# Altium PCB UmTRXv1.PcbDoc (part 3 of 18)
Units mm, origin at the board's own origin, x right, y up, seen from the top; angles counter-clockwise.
Board outline 172 x 113 mm, 6 copper layers (Top Layer, GND, MidLayer1, Mid-Layer 2, InternalPlane2, Bottom Layer); 766 components, 613 nets, 3008 pads, 1360 vias.
Unrouted connection lines stored in the file: 2.
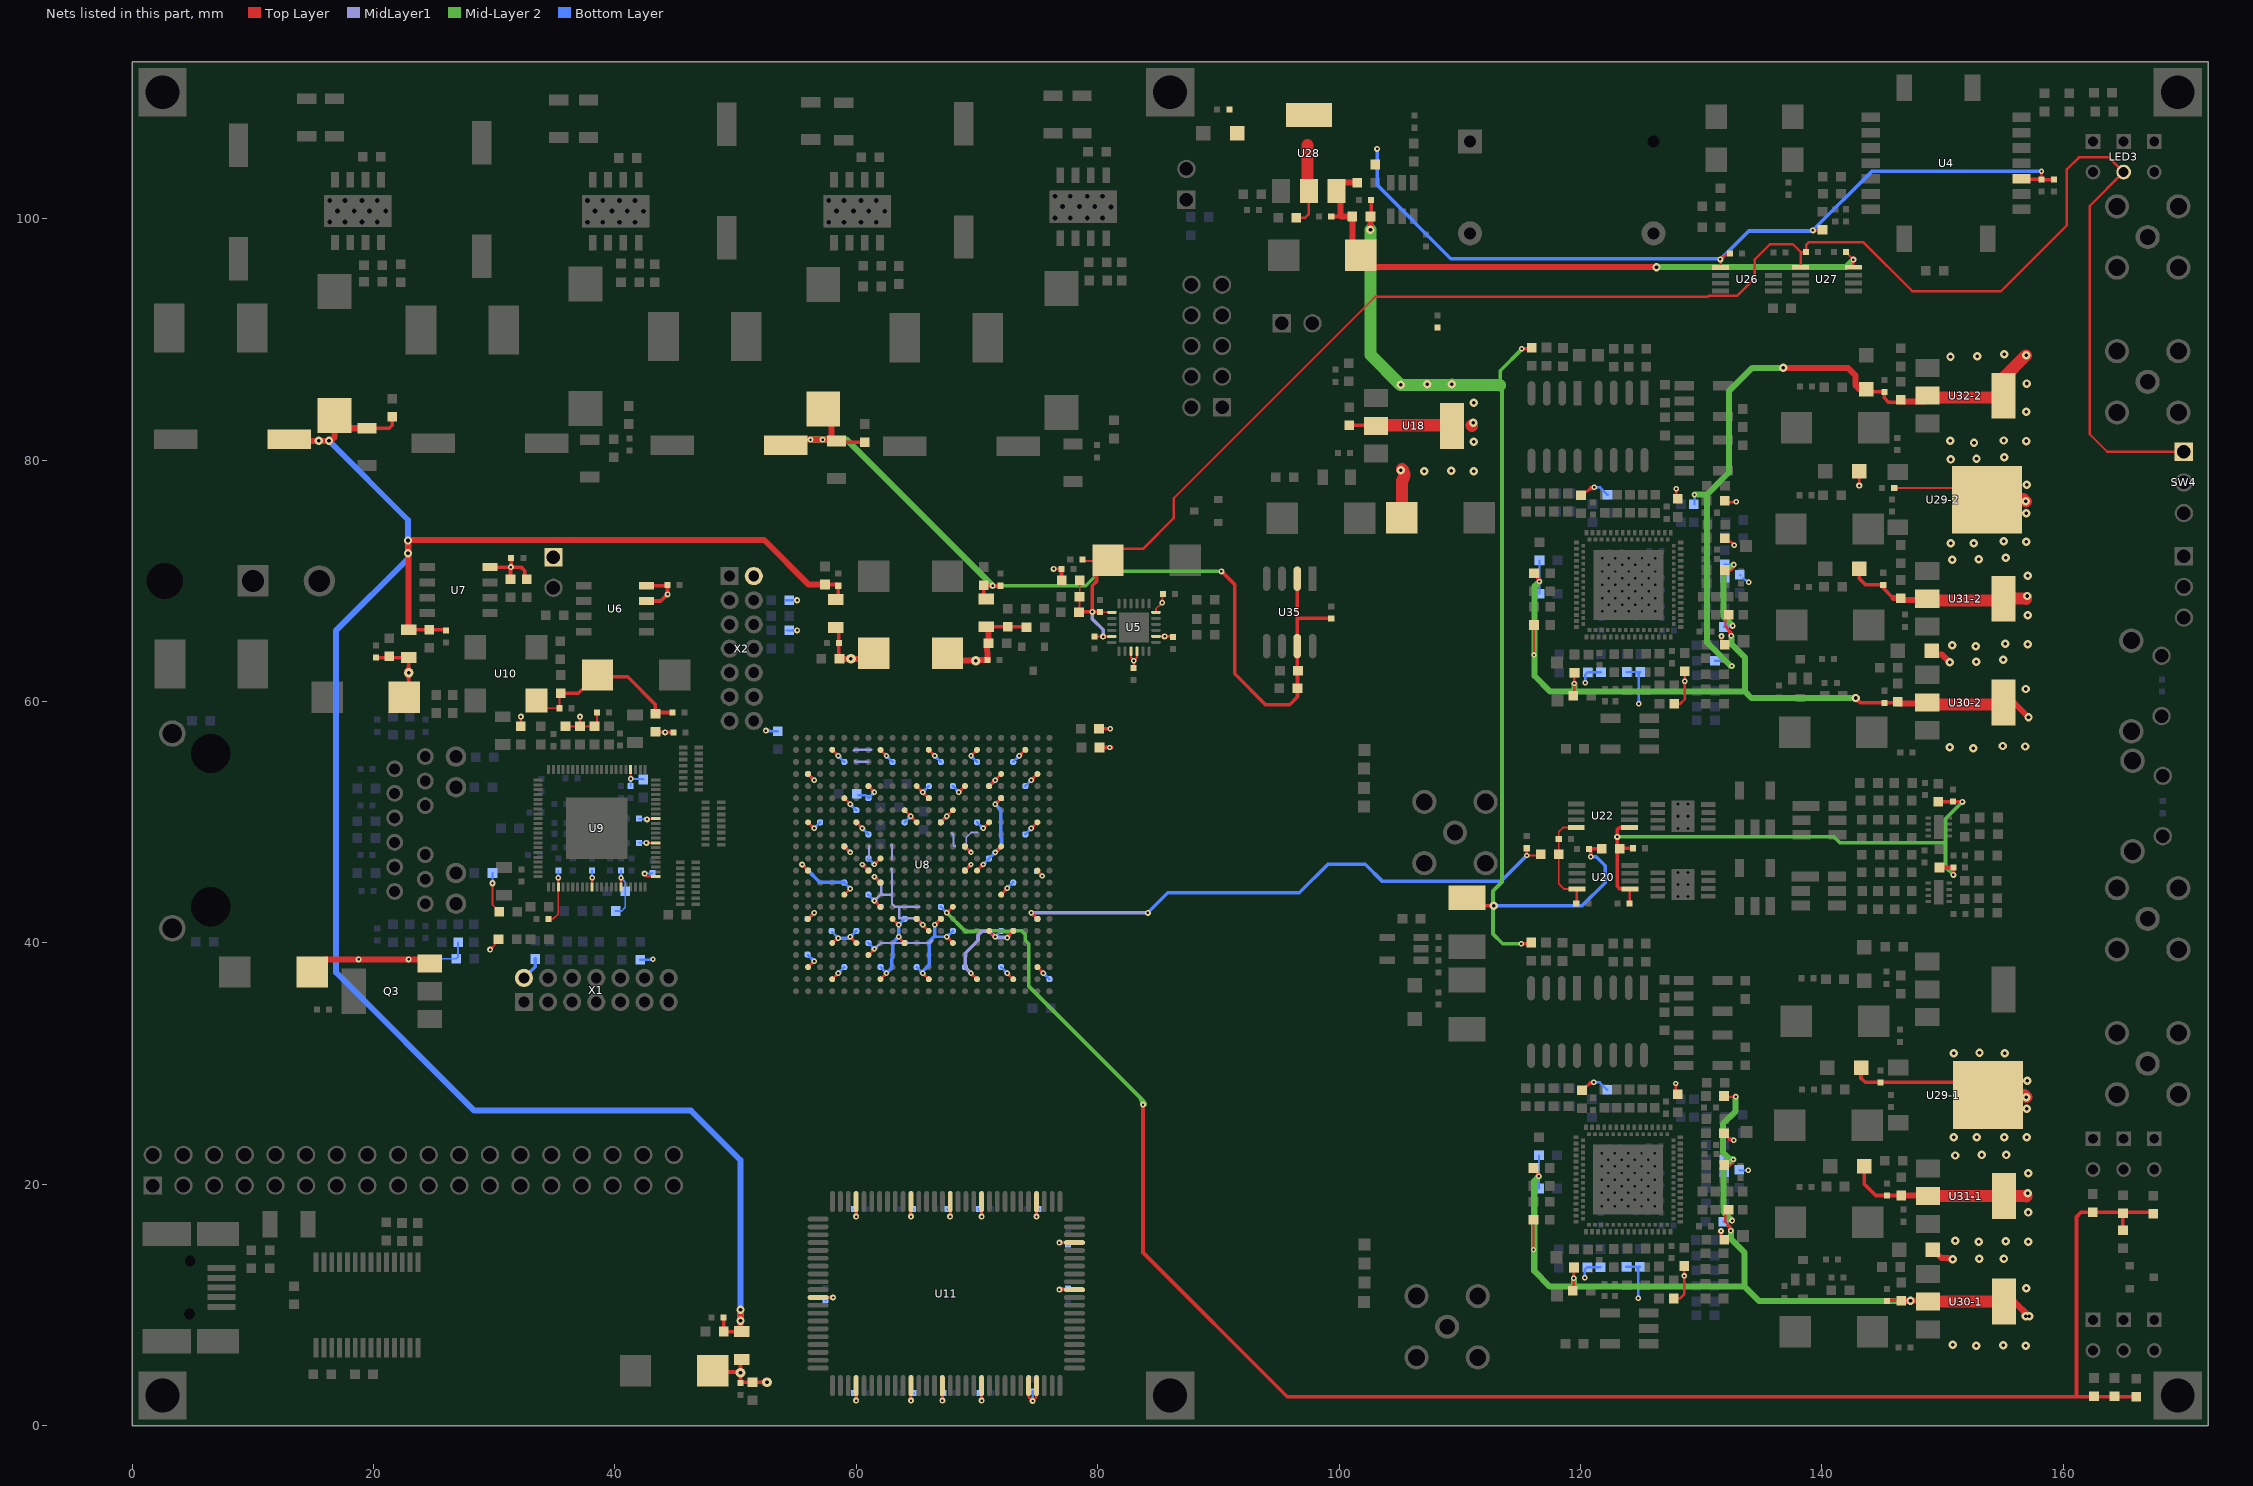
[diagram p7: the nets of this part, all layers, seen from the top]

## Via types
v1: diameter 0.45, hole 0.2, Top Layer to Bottom Layer, tented both sides, 554 vias
v2: diameter 0.5, hole 0.2, Top Layer to Bottom Layer, tented both sides, 468 vias
v3: diameter 0.7, hole 0.3, Top Layer to Bottom Layer, tented both sides, 206 vias
v4: diameter 0.4, hole 0.2, Top Layer to Bottom Layer, tented both sides, 82 vias
v5: diameter 0.8, hole 0.3, Top Layer to Bottom Layer, tented both sides, 16 vias
v6: diameter 0.6, hole 0.25, Top Layer to Bottom Layer, tented both sides, 16 vias
v7: diameter 0.5, hole 0.3, Top Layer to Bottom Layer, tented both sides, 8 vias
v8: diameter 0.7, hole 0.3, Top Layer to Bottom Layer, 4 vias
v9: diameter 0.6, hole 0.3, Top Layer to Bottom Layer, tented both sides, 4 vias
v10: diameter 0.5, hole 0.2, Top Layer to Bottom Layer, 2 vias

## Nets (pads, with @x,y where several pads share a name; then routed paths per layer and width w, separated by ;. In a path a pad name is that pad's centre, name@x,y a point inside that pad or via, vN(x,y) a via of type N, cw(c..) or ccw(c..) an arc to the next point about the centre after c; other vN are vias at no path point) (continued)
+1,8VALMS-2: C67-2.1 C72-2.1 L14-2.1 L15-2.1 R101-2.2 U32-2.2 | length 58.8
  Top Layer w0.3: C67-2.1@143.9,85.8 144.037,85.663 145.161,85.663 145.161,85.167 145.507,84.821 146.322,84.821 R101-2.2@146.352,84.85
  Top Layer w0.5: v3(136.8,87.65) 142.15,87.65 142.8,87 142.8,86.2 143.15,85.85 C67-2.1@144.05,85.85 ; R101-2.2@146.352,84.85 148.55,84.85 U32-2.2@148.55,85.2
  Top Layer w1: U32-2.2@148.55,85.2 U32-2.2@154.85,85.2 ; U32-2.2@155.05,85.35 155.05,86.82 v3(156.925,88.696)
  Mid-Layer 2 w0.5: v1(129.45,77.15) 130.462,77.15 ; v1(132.55,62.95) 132.437,62.95 130.483,64.904 130.483,77.13 130.462,77.15 ; v3(136.8,87.65) 136.8,87.6 136.75,87.65 134.25,87.65 132.3,85.7 132.3,78.988 130.462,77.15
  Bottom Layer w0.2: v1@129.362,77.062 cw(c129.148,76.848) 129.45,76.848 cw(c129.752,76.848) v1@129.538,77.062 ; L15-2.1@129.45,76.35 v1(129.45,77.15) ; L14-2.1@131.146,63.38 132.12,63.38 v1(132.55,62.95) ; v1@132.425,62.95 ccw(c132.123,62.95) 132.337,63.163 ccw(c132.55,63.377) v1@132.55,63.075
  other v3: 152.611,81.442 150.65,81.6 156.925,81.592 155.063,81.636 156.925,84.018 156.969,86.357 150.661,88.589 152.87,88.632 155.106,88.782
+1,8VDLMS-1: C66-1.1 C71-1.1 L11-1.2 L16-1.2 L18-1.2 L19-1.2 L20-1.2 R100-1.2 U31-1.2 | length 23.3
  Top Layer w0.2: v2@131.542,16.03 cw(c131.273,15.761) L19-1.2@131.654,15.761 ; L19-1.2@131.654,15.495 v2@131.654,16.069 ; L19-1.2@131.654,15.787 cw(c131.997,15.787) v2@131.754,16.03 ; L19-1.2@131.907,15.588 L19-1.2@132.037,15.458 ; L16-1.2@131.907,24.188 131.907,24.143 132.4,23.65 ; L16-1.2@131.974,24.076 ccw(c132.7,24.801) v1@132.7,23.775 ; 132.316,23.734 ccw(c132.7,24.118) v1@132.7,23.575 ; v1@132.611,23.562 ccw(c132.4,23.353) 132.4,23.65 ; v1@132.611,23.738 cw(c132.4,23.947) 132.4,23.65 ; v1(132.7,23.65) 132.4,23.65
  Top Layer w0.3: C66-1.1@143.5,21.5 143.5,20.05 144.473,19.077 C71-1.1@145.39,19.077 ; C71-1.1@145.35,19.077 R100-1.2@146.59,19.077
  Top Layer w0.5: R100-1.2@146.59,19.077 148.74,19.077 U31-1.2@148.79,19.027
  Top Layer w1: U31-1.2@148.79,19.027 U31-1.2@155.09,19.027 156.938,19.027 v3@156.972,18.993
  Bottom Layer w0.15: L18-1.2@133.161,21.208 133.211,21.158 v1(133.911,21.158) ; v1@133.805,21.052 ccw(c133.549,20.796) 133.549,21.158 ccw(c133.549,21.52) v1@133.805,21.264
  Bottom Layer w0.2: v1@120.273,12.347 ccw(c120.059,12.56) 120.361,12.56 ccw(c120.663,12.56) v1@120.449,12.347 ; v1(120.361,12.258) 120.361,12.942 L20-1.2@120.557,13.138 L11-1.2@121.657,13.138
  other v2: 131.648,16.136
  other v3: 152.995,15.244 157.109,15.244 155.247,15.287 151.046,15.33 157.109,17.669 157.059,19.253 157.116,20.917 151.046,22.39 153.255,22.434 155.29,22.434
+1,8VDLMS-2: C66-2.1 C71-2.1 L11-2.2 L16-2.2 L18-2.2 L19-2.2 L20-2.2 R100-2.2 U31-2.2 | length 22.6
  Top Layer w0.2: v2@131.581,65.322 cw(c131.312,65.053) L19-2.2@131.693,65.053 ; L19-2.2@131.693,64.787 v2@131.693,65.361 ; L19-2.2@131.693,65.079 cw(c132.036,65.079) v2@131.793,65.322 ; L19-2.2@131.946,64.88 L19-2.2@132.076,64.75 ; L16-2.2@131.946,73.48 131.946,73.354 132.05,73.25 132.45,73.25 132.65,73.05 v1@132.65,72.85 ; v1@132.625,72.95 ccw(c132.323,72.95) 132.537,73.163 ccw(c132.75,73.377) v1@132.75,73.075
  Top Layer w0.3: C66-2.1@143.1,71 143.1,70.2 143.624,69.676 C71-2.1@145.09,69.676 145.09,69.41 145.924,68.576
  Top Layer w0.5: 145.924,68.576 R100-2.2@146.54,68.576 ; R100-2.2@146.34,68.426 148.49,68.426 U31-2.2@148.54,68.376
  Top Layer w1: U31-2.2@148.54,68.376 U31-2.2@154.84,68.376 ; U31-2.2@155.04,68.526 156.888,68.526 v3@156.922,68.492
  Bottom Layer w0.15: L18-2.2@133.2,70.5 L18-2.2@133.25,70.45 ; 133.699,70.001 ccw(c133.943,70.245) v1(133.95,69.9) ; v1@133.947,70.05 cw(c133.933,70.733) 133.45,70.25 133.775,69.925 133.85,70 v1@133.95,70.1
  Bottom Layer w0.2: v1@120.312,61.638 ccw(c120.098,61.852) 120.4,61.852 ccw(c120.702,61.852) v1@120.488,61.638 ; v1(120.4,61.55) 120.4,62.234 L20-2.2@120.596,62.43 L11-2.2@121.696,62.43
  other v1: 132.75,72.95
  other v2: 131.687,65.428
  other v3: 152.745,64.593 150.796,64.68 157.059,64.743 155.197,64.786 157.059,67.169 157.009,68.752 157.066,70.416 150.796,71.74 153.005,71.783 155.24,71.933
+2,5V1: C137.1 C140.1 C143.1 C144.1 C145.1 C151.1 C152.1 C153.1 L37.1 L41.1 L42.1 L43.1 R137.1 | length 169.2
  Top Layer w0.3: L37.1@16.4,82.75 16.55,82.9 16.75,82.7 L37.1@16.8,82.65 ; C137.1@19.45,82.65 21.3,82.65 21.55,82.9 R137.1@21.55,83.6 ; L42.1@22.9,65.95 25.95,65.95 C144.1@26,65.9 ; C145.1@49,8.95 C153.1@49,7.8 L43.1@50.5,7.8 ; C151.1@57.4,69.7 58.45,69.7 C143.1@58.5,69.65 ; L41.1@58.3,68.45 58.5,68.65 C143.1@58.5,69.6
  Top Layer w0.5: C140.1@13,81.75 13.15,81.6 v3(15.45,81.6) v3(16.3,81.6) 16.45,81.6 16.75,81.9 16.75,82.7 L37.1@16.75,83.7 17.8,82.65 C137.1@19.45,82.65 ; v3@22.779,73.279 cw(c22.488,72.988) 22.9,72.988 ; L42.1@22.9,65.95 22.9,73.3 v3(22.85,73.35) 22.9,73.4 52.35,73.4 56.05,69.7 C151.1@57.05,69.7 ; v3@22.921,73.279 cw(c23.212,72.988) 23.212,73.4 ; v3@50.4,9.4 v3(50.4,8.7) 50.4,7.9 L43.1@50.5,7.8
  Bottom Layer w0.5: v3(15.45,81.6) v3(16.3,81.6) 22.85,75.05 v3(22.85,73.35) v3(22.85,72.3) 22.85,71.85 16.9,65.9 16.9,37.55 28.35,26.1 46.3,26.1 50.4,22 v3(50.4,9.6) v3(50.4,8.7)
+2,5VCC: C14.2 C15.2 C17.1 C18.1 C19.1 C20.1 C21.1 C22.1 C314.1 L3.1 LED3.5 R11.1 SW4.1 U5.7 U5.11 U5.15 U5.16 U5.20 U5.24 U27.1 | length 166.6
  Top Layer w0.15: R11.1@78.45,67.4 78.487,67.437 C19.1@78.487,68.687 ; C19.1@78.524,68.65 C19.1@78.487,68.687 ; L3.1@78.523,70.054 L3.1@78.513,70.043 78.513,68.713 C19.1@78.487,68.687 ; R11.1@78.651,67.388 79.45,67.388 79.462,67.4 U5.7@81.175,67.4 ; C18.1@78.673,71.812 C18.1@78.723,71.762 ; C18.1@78.723,71.662 C17.1@79.673,71.662 ; 79.007,67.388 ccw(c79.007,67.981) v2@79.426,67.561 ; 79.248,67.388 cw(c79.248,67.136) v2@79.426,67.314 ; v2@79.674,67.314 cw(c79.882,67.106) 79.882,67.4 ; v2@79.674,67.561 ccw(c80.063,67.951) C15.2@80.063,67.4 ; C14.2@79.9,65.388 v2(80.45,65.388) ; v2@80.326,65.264 ccw(c80.027,64.965) 80.027,65.388 ccw(c80.027,65.81) v2@80.326,65.511 ; v2@80.5,65.388 80.55,65.388 80.562,65.4 U5.11@81.175,65.4 ; v2@80.574,65.264 cw(c80.902,64.935) U5.11@80.902,65.4 ; v2@80.574,65.511 ccw(c80.842,65.78) U5.11@80.842,65.4 ; U5.15@82.75,64.175 82.75,63.65 ; v1@82.85,63.403 ccw(c82.508,63.408) 82.75,63.65 ; v1@82.894,63.294 cw(c82.638,63.038) 83,63.038 cw(c83.362,63.038) v1@83.106,63.294 ; C22.1@82.95,62.8 83,62.85 v1(83,63.4) ; v1@82.997,63.55 cw(c82.992,63.892) 82.75,63.65 ; v1@83.003,63.55 ccw(c83.008,63.892) 83.25,63.65 ; v1@83.15,63.403 cw(c83.492,63.408) 83.25,63.65 ; U5.16@83.25,64.175 83.25,63.65 ; U5.24@84.825,67.4 84.825,67.675 v1(85.35,68.2) 85.35,68.85 C21.1@85.4,68.9 ; v1@85.2,68.2 cw(c84.838,68.2) 85.094,67.944 cw(c85.35,67.688) v1@85.35,68.05 ; v1@85.244,68.306 ccw(c84.988,68.562) 85.35,68.562 ccw(c85.712,68.562) v1@85.456,68.306 ; 82.75,63.65 v1(83,63.4) ; v1(83,63.4) 83.25,63.65
  Top Layer w0.2: C17.1@80.85,71.7 81.8,72.65 83.75,72.65 86.3,75.2 86.3,76.85 103,93.55 130.536,93.55 130.611,93.625 130.82,93.625 130.825,93.621 132.971,93.621 134.45,95.1 134.45,96.65 135.7,97.9 137.6,97.9 138.25,97.25 ; U5.20@84.825,65.4 v2(85.55,65.4) C20.1@86.25,65.4 ; v2@85.444,65.294 ccw(c85.188,65.038) 85.188,65.4 ccw(c85.188,65.762) v2@85.444,65.506 ; v2@85.656,65.294 cw(c85.912,65.038) 85.912,65.4 cw(c85.912,65.762) v2@85.656,65.506 ; U27.1@138.221,95.986 138.25,96.015 138.25,97.25 ; SW4.1@170,80.7 163.65,80.7 162.2,82.15 162.2,101.07 LED3.5@165.01,103.88 163.79,105.1 161.3,105.1 160.3,104.1 160.3,99.45 154.85,94 147.5,94 143.45,98.05 138.9,98.05 138.7,97.85 C314.1@138.7,97.25 138.25,97.25
  Top Layer w0.3: R11.1@78.627,67.438 79.45,67.438 v2@79.45,67.388 ; C17.1@79.9,70.4 79.9,69.95 79.55,69.6 v2(79.55,67.438) C15.2@80.2,67.438
  MidLayer1 w0.3: v2(79.55,67.438) 79.55,66.85 80.45,65.95 v2(80.45,65.388)
+2,5VETH: C40.1 C41.2 C157.1 C163.1 C167.1 C171.1 C228.2 C229.1 C230.1 C231.1 C232.1 C233.1 C234.1 C235.1 L4.1 L42.2 L45.1 LED5.2 LED6.2 Q3.3 R41.2 R46.2 R52.1 R53.1 R54.1 R91.1 R92.1 U9.4 U9.45 U9.52 U9.58 U9.64 U9.71 U9.76 | length 64
  Top Layer w0.15: Q3.3@24.65,38.3 Q3.3@24.7,38.35 ; v2(29.65,39.45) 30.3,40.1 LED6.2@30.35,40.1 ; v2@29.65,39.625 ccw(c29.65,40.047) 29.949,39.749 ccw(c30.247,39.45) v2@29.825,39.45 ; v2@29.726,44.826 cw(c29.428,44.528) 29.85,44.528 cw(c30.272,44.528) v2@29.974,44.826 ; v2(29.85,44.95) 29.85,43.15 LED5.2@30.4,42.6 ; v2@32.076,58.626 cw(c31.778,58.328) 32.2,58.328 cw(c32.622,58.328) v2@32.324,58.626 ; L45.1@32.2,57.95 v2(32.2,58.75) ; C228.2@34.5,42 34.9,42 35.3,42.4 U9.45@35.3,44.625 v1(35.3,45.4) ; v1@35.194,45.294 cw(c34.938,45.038) 35.3,45.038 cw(c35.662,45.038) v1@35.406,45.294 ; R54.1@35.9,57.95 R53.1@37.1,57.95 ; v2@36.976,58.626 cw(c36.678,58.328) 37.1,58.328 cw(c37.522,58.328) v2@37.224,58.626 ; v2(37.1,58.75) R53.1@37.1,57.95 ; v1@37.994,45.294 cw(c37.738,45.038) 38.1,45.038 cw(c38.462,45.038) v1@38.206,45.294 ; U9.52@38.1,44.625 v1(38.1,45.4) ; C40.1@38.5,59.1 38.5,58.15 R52.1@38.3,57.95 R53.1@37.1,57.95 ; v1@40.394,45.294 cw(c40.138,45.038) 40.5,45.038 cw(c40.862,45.038) v1@40.606,45.294 ; U9.58@40.5,44.625 v1(40.5,45.4) ; v1@41.194,53.706 ccw(c40.938,53.962) 41.3,53.962 ccw(c41.662,53.962) v1@41.406,53.706 ; v1(41.3,53.6) U9.4@41.3,54.375 ; v2(42.45,45.75) 42.45,45.7 42.65,45.5 ; v2@42.457,45.575 cw(c42.468,45.318) 42.65,45.5 ; v2(42.6,48.3) U9.71@43.375,48.3 ; v2@42.612,45.685 ccw(c42.771,45.621) 42.65,45.5 ; v2(42.65,50.25) 42.7,50.3 U9.76@43.375,50.3 ; v2@42.724,48.176 cw(c43.022,47.878) 43.022,48.3 cw(c43.022,48.722) v2@42.724,48.424 ; U9.64@43.375,45.5 42.65,45.5
  Top Layer w0.3: C157.1@20.2,63.65 L42.2@22.9,63.65 v5(22.9,62.4) 22.9,60.7 C167.1@22.55,60.35 ; v5@22.723,62.223 cw(c22.296,61.796) 22.9,61.796 cw(c23.504,61.796) v5@23.077,62.223 ; v5@22.723,62.577 ccw(c22.296,63.004) 22.9,63.004 ccw(c23.504,63.004) v5@23.077,62.577
  Top Layer w0.5: C171.1@14.9,37.6 15.95,38.65 v2(18.75,38.65) v2(22.9,38.65) 24.3,38.65 Q3.3@24.65,38.3
  Bottom Layer w0.15: v2(22.9,38.65) 22.95,38.7 R46.2@26.85,38.7 27,38.85 L4.1@27,40.05 ; v2@23.024,38.526 cw(c23.443,38.107) 23.443,38.7 ; v2@23.024,38.774 ccw(c23.202,38.952) 23.202,38.7 ; v2@29.726,45.074 ccw(c29.428,45.372) 29.85,45.372 ccw(c30.272,45.372) v2@29.974,45.074 ; v2(29.85,44.95) R41.2@29.85,45.8 ; v1@35.194,45.506 ccw(c34.938,45.762) 35.3,45.762 ccw(c35.662,45.762) v1@35.406,45.506 ; v1(35.3,45.4) C229.1@35.3,46 ; v1@37.994,45.506 ccw(c37.738,45.762) 38.1,45.762 ccw(c38.462,45.762) v1@38.206,45.506 ; v1(38.1,45.4) C232.1@38.1,46 ; R91.1@40.05,42.65 40.55,42.65 40.85,42.95 R92.1@40.85,44.287 40.85,45.05 v1(40.5,45.4) C233.1@40.5,46 ; v1@40.394,45.506 ccw(c40.138,45.762) 40.5,45.762 ccw(c40.862,45.762) v1@40.606,45.506 ; v1@40.5,45.25 cw(c40.5,44.888) 40.756,45.144 cw(c41.012,45.4) v1@40.65,45.4 ; v1@41.194,53.494 cw(c40.938,53.238) 41.3,53.238 cw(c41.662,53.238) 41.406,53.494 cw(c41.662,53.238) 41.662,53.6 cw(c41.662,53.962) v1@41.406,53.706 ; C230.1@41.3,53 v1(41.3,53.6) 42.3,53.6 C41.2@42.35,53.55 ; C231.1@42,48.3 v2(42.6,48.3) ; C234.1@42,50.3 42.6,50.3 v2(42.65,50.25) ; C234.1@42.107,50.3 cw(c42.107,49.707) v2@42.526,50.126 ; 42.348,50.3 ccw(c42.348,50.552) v2@42.526,50.374 ; v2(42.45,45.75) 43.05,45.75 C235.1@43.1,45.8 ; v2@42.476,48.176 ccw(c42.178,47.878) 42.178,48.3 ccw(c42.178,48.722) v2@42.476,48.424 ; v2@42.574,45.626 cw(c42.872,45.328) 42.872,45.75 cw(c42.872,46.172) v2@42.574,45.874
+2,5VFPGA: C24.1 C156.1 C162.1 C166.1 C172.2 C175.2 C176.2 C177.2 C178.2 C179.2 C180.2 C181.2 C182.2 C183.2 C184.2 C185.2 C186.2 C187.2 C188.2 C189.2 C190.2 C191.2 C192.2 C193.2 C204.2 C205.2 C206.2 C207.2 C208.2 C209.2 C210.2 C211.2 C212.2 C213.2 C289.1 L3.2 L41.2 L48.1 U8.B4 U8.B7 U8.B11 U8.B15 U8.B19 U8.C2 U8.C21 U8.E9 U8.E13 U8.E17 U8.E19 U8.F4 U8.F6 U8.G2 U8.G10 U8.G14 U8.G21 U8.J5 U8.J18 U8.L2 U8.L7 U8.L16 U8.L21 U8.N5 U8.N18 U8.R2 U8.R21 U8.U5 U8.U18 U8.W2 U8.W21 | length 159.1
  Top Layer w0.2: v2@55.5,46.35 cw(c55.5,45.988) 55.756,46.244 cw(c56.012,46.5) v2@55.65,46.5 ; v2(55.5,46.5) U8.L21@56,46 ; U8.C21@56,38 v1(56.5,38.5) ; U8.G21@56,42 v1(56.5,42.5) ; U8.R21@56,50 v1(56.5,49.5) ; U8.W21@56,54 v1(56.5,53.5) ; v1@56.35,38.5 cw(c55.988,38.5) 56.244,38.244 cw(c56.5,37.988) v1@56.5,38.35 ; v1@56.35,42.5 cw(c55.988,42.5) 56.244,42.244 cw(c56.5,41.988) v1@56.5,42.35 ; v1@56.35,49.5 ccw(c55.988,49.5) 56.244,49.756 ccw(c56.5,50.012) v1@56.5,49.65 ; v1@56.35,53.5 ccw(c55.988,53.5) 56.244,53.756 ccw(c56.5,54.012) v1@56.5,53.65 ; U8.B19@58,37 v1(58.5,37.5) ; U8.E19@58,40 v1@58.5,40.5 ; U8.E19@58.073,40.073 cw(c58.5,39.646) v1@58.5,40.25 ; v1@58.35,37.5 cw(c57.988,37.5) 58.244,37.244 cw(c58.5,36.988) v1@58.5,37.35 ; U8.J18@59,44 v1(59.5,44.5) ; U8.N18@59,48 v1(59.5,47.5) ; U8.U18@59,52 v1(59.5,51.5) ; v1@59.35,44.5 cw(c58.988,44.5) 59.244,44.244 cw(c59.5,43.988) v1@59.5,44.35 ; v1@59.35,47.5 ccw(c58.988,47.5) 59.244,47.756 ccw(c59.5,48.012) v1@59.5,47.65 ; v1@59.35,51.5 ccw(c58.988,51.5) 59.244,51.756 ccw(c59.5,52.012) v1@59.5,51.65 ; v1@59.5,40.35 cw(c59.5,39.988) 59.756,40.244 cw(c60.012,40.5) v1@59.65,40.5 ; v1(59.5,40.5) U8.E17@60,40 ; v1@60.5,46.35 cw(c60.5,45.988) 60.756,46.244 cw(c61.012,46.5) v1@60.65,46.5 ; v1(60.5,46.5) U8.L16@61,46 ; U8.B15@62,37 v1(62.5,37.5) ; v1@62.35,37.5 cw(c61.988,37.5) 62.244,37.244 cw(c62.5,36.988) v1@62.5,37.35 ; U8.G14@63,42 v1(63.5,41.5) ; v1@63.35,41.5 ccw(c62.988,41.5) 63.244,41.756 ccw(c63.5,42.012) v1@63.5,41.65 ; v1@63.5,40.35 cw(c63.5,39.988) 63.756,40.244 cw(c64.012,40.5) v1@63.65,40.5 ; v1(63.5,40.5) U8.E13@64,40 ; v1@65.5,37.35 cw(c65.5,36.988) 65.756,37.244 cw(c66.012,37.5) v1@65.65,37.5 ; v1(65.5,37.5) U8.B11@66,37 ; v1(66.5,41.5) U8.G10@67,42 ; v1@66.5,41.65 ccw(c66.5,42.012) 66.756,41.756 ccw(c67.012,41.5) v1@66.65,41.5 ; v1@67.5,40.35 cw(c67.5,39.988) 67.756,40.244 cw(c68.012,40.5) v1@67.65,40.5 ; v1(67.5,40.5) U8.E9@68,40 ; v1@69.5,37.35 cw(c69.5,36.988) 69.756,37.244 cw(c70.012,37.5) v1@69.65,37.5 ; v1(69.5,37.5) U8.B7@70,37 ; U8.L7@70,46 v1(70.5,46.5) ; v1@70.35,46.5 cw(c69.988,46.5) 70.244,46.244 cw(c70.5,45.988) v1@70.5,46.35 ; U8.F6@71,41 v1(71.5,40.5) ; v1@71.35,40.5 ccw(c70.988,40.5) 71.244,40.756 ccw(c71.5,41.012) v1@71.5,40.65 ; v1(71.5,47.5) U8.N5@72,48 ; v1@71.5,47.65 ccw(c71.5,48.012) 71.756,47.756 ccw(c72.012,47.5) v1@71.65,47.5 ; v1(71.5,51.5) U8.U5@72,52 ; v1@71.5,51.65 ccw(c71.5,52.012) 71.756,51.756 ccw(c72.012,51.5) v1@71.65,51.5 ; U8.J5@72,44 v1@72.5,44.5 ; 72.209,44.209 ccw(c71.867,44.55) v1@72.35,44.55 ; 72.329,44.329 cw(c72.5,44.158) v1@72.5,44.4 ; v1@72.5,37.35 cw(c72.5,36.988) 72.756,37.244 cw(c73.012,37.5) v1@72.65,37.5 ; v1(72.5,37.5) U8.B4@73,37 ; v1@72.5,40.5 U8.F4@73,41 ; v1@72.5,40.6 ccw(c72.5,40.841) 72.671,40.671 ; v1@72.65,40.45 cw(c73.133,40.45) 72.791,40.791 ; v1@74.5,42.35 cw(c74.5,41.987) 74.756,42.244 cw(c75.011,42.5) v1@74.65,42.5 ; v1(74.5,42.5) U8.G2@75,42 ; v1(74.5,49.5) U8.R2@75,50 ; v1@74.5,49.65 ccw(c74.5,50.012) 74.756,49.756 ccw(c75.012,49.5) v1@74.65,49.5 ; v1(74.5,53.5) U8.W2@75,54 ; v1@74.5,53.65 ccw(c74.5,54.012) 74.756,53.756 ccw(c75.012,53.5) v1@74.65,53.5 ; U8.L2@74.9,46.05 v1(75.4,45.55) ; U8.C2@75,38 v1(75.5,37.5) ; v1@75.25,45.55 ccw(c74.888,45.55) 75.144,45.806 ccw(c75.4,46.062) v1@75.4,45.7 ; v1@75.35,37.5 ccw(c74.988,37.5) 75.244,37.756 ccw(c75.5,38.012) v1@75.5,37.65 ; v2(76.35,71) C24.1@77,71 ; v2@76.456,70.894 cw(c76.712,70.638) 76.712,71 cw(c76.712,71.362) v2@76.456,71.106 ; v1@115.462,47.338 ccw(c115.248,47.552) 115.55,47.552 ccw(c115.852,47.552) 115.638,47.338 ccw(c115.852,47.552) 115.852,47.25 ccw(c115.852,46.948) v1@115.638,47.162 ; C289.1@115.55,47.85 v1(115.55,47.25) 116.6,47.25 L48.1@116.7,47.35
  Top Layer w0.3: L41.2@58.3,66.15 58.55,65.9 C156.1@58.55,64.85 58.55,63.6 C162.1@58.6,63.55 ; C166.1@61,63.55 C166.1@61.45,64 ; L3.2@77,70.244 C24.1@77,71
  Top Layer w0.5: C162.1@58.6,63.55 v5(59.55,63.55) C166.1@61,63.55
  MidLayer1 w0.3: v1(69.5,37.5) 69.025,37.975 69.025,39.15 70.102,40.227 70.075,40.253 70.075,40.647 70.403,40.975 71.025,40.975 v1(71.5,40.5) 71.55,40.45 v1(72.5,40.45) ; v1(74.5,42.5) 84.1,42.5 v2(84.15,42.5)
  Bottom Layer w0.2: v2@55.5,46.35 cw(c55.5,45.988) 55.756,46.244 cw(c56.012,46.5) v2@55.65,46.5 ; v2(55.5,46.5) C212.2@56,46 ; C185.2@56,39 v1(56.5,38.5) ; C209.2@56,42 v1(56.5,42.5) ; C186.2@56,54 v1(56.5,53.5) ; v1@56.35,38.5 ccw(c55.988,38.5) 56.244,38.756 ccw(c56.5,39.012) v1@56.5,38.65 ; v1@56.35,42.5 cw(c55.988,42.5) 56.244,42.244 cw(c56.5,41.988) v1@56.5,42.35 ; v1@56.35,53.5 ccw(c55.988,53.5) 56.244,53.756 ccw(c56.5,54.012) v1@56.5,53.65 ; v1(56.5,49.5) C211.2@57,50 ; v1@56.5,49.65 ccw(c56.5,50.012) 56.756,49.756 ccw(c57.012,49.5) v1@56.65,49.5 ; C208.2@58,40.9 v1(58.5,40.4) v1@58.5,40.5 ; v1@58.35,40.4 ccw(c57.988,40.4) 58.244,40.656 ccw(c58.5,40.912) v1@58.5,40.55 ; v1(58.5,37.5) C176.2@59,38 ; v1@58.5,37.65 ccw(c58.5,38.012) 58.756,37.756 ccw(c59.012,37.5) v1@58.65,37.5 ; C210.2@59,45 v1(59.5,44.5) ; C213.2@59,48 v1(59.5,47.5) ; v1@59.35,44.5 ccw(c58.988,44.5) 59.244,44.756 ccw(c59.5,45.012) v1@59.5,44.65 ; v1@59.35,47.5 ccw(c58.988,47.5) 59.244,47.756 ccw(c59.5,48.012) v1@59.5,47.65 ; v1(59.5,40.5) C184.2@60,41 ; v1@59.5,40.65 ccw(c59.5,41.012) 59.756,40.756 ccw(c60.012,40.5) v1@59.65,40.5 ; v1@59.5,51.35 cw(c59.5,50.988) 59.756,51.244 cw(c60.012,51.5) v1@59.65,51.5 ; v1(59.5,51.5) C177.2@60,51 ; v1@60.5,46.35 cw(c60.5,45.988) 60.756,46.244 cw(c61.012,46.5) v1@60.65,46.5 ; v1(60.5,46.5) C172.2@61,46 ; C187.2@62,38 v1(62.5,37.5) ; v1@62.35,37.5 ccw(c61.988,37.5) 62.244,37.756 ccw(c62.5,38.012) v1@62.5,37.65 ; v1@63.5,40.35 cw(c63.5,39.988) 63.756,40.244 cw(c64.012,40.5) v1@63.65,40.5 ; v1(63.5,40.5) C183.2@64,40 ; v1(63.5,41.5) C206.2@64,42 ; v1@63.5,41.65 ccw(c63.5,42.012) 63.756,41.756 ccw(c64.012,41.5) v1@63.65,41.5 ; C188.2@65,38 v1(65.5,37.5) ; v1@65.35,37.5 ccw(c64.988,37.5) 65.244,37.756 ccw(c65.5,38.012) v1@65.5,37.65 ; 66.5,40.575 66.575,40.5 v1(67.5,40.5) C204.2@68,41 ; v1(66.5,41.5) C182.2@67,42 ; v1@66.5,41.65 ccw(c66.5,42.012) 66.756,41.756 ccw(c67.012,41.5) v1@66.65,41.5 ; v1@67.5,40.65 ccw(c67.5,41.012) 67.756,40.756 ccw(c68.012,40.5) v1@67.65,40.5 ; C189.2@69,38 v1(69.5,37.5) ; v1@69.35,37.5 ccw(c68.988,37.5) 69.244,37.756 ccw(c69.5,38.012) v1@69.5,37.65 ; v1(70.5,46.5) C175.2@71,47 v1(71.5,47.5) ; v1@70.5,46.65 ccw(c70.5,47.012) 70.756,46.756 ccw(c71.012,46.5) v1@70.65,46.5 ; v1@71.35,47.5 cw(c70.988,47.5) 71.244,47.244 cw(c71.5,46.988) v1@71.5,47.35 ; v1(71.5,40.5) C193.2@72,41 ; v1@71.5,40.65 ccw(c71.5,41.012) 71.756,40.756 ccw(c72.012,40.5) v1@71.65,40.5 ; v1(71.5,51.5) C178.2@72,52 ; v1@71.5,51.65 ccw(c71.5,52.012) 71.756,51.756 ccw(c72.012,51.5) v1@71.65,51.5 ; C190.2@72,38 v1(72.5,37.5) ; v1@72.35,37.5 ccw(c71.988,37.5) 72.244,37.756 ccw(c72.5,38.012) v1@72.5,37.65 ; v1(72.5,40.45) 72.5,40.5 C181.2@73,41 ; v1@72.5,40.6 ccw(c72.5,40.841) 72.671,40.671 ; v1@72.5,44.5 v1(72.5,44.55) C205.2@73,45.05 ; v1@72.5,44.7 ccw(c72.5,45.062) 72.756,44.806 ccw(c73.012,44.55) v1@72.65,44.55 ; v1@72.65,40.45 cw(c73.133,40.45) 72.791,40.791 ; C192.2@74,49 v1(74.5,49.5) ; C207.2@74,53 v1(74.5,53.5) ; v1@74.35,49.5 cw(c73.988,49.5) 74.244,49.244 cw(c74.5,48.988) v1@74.5,49.35 ; v1@74.35,53.5 cw(c73.988,53.5) 74.244,53.244 cw(c74.5,52.988) v1@74.5,53.35 ; v1@74.5,42.35 cw(c74.5,41.987) 74.756,42.244 cw(c75.011,42.5) v1@74.65,42.5 ; v1(74.5,42.5) C180.2@75,42 ; C179.2@74.9,46.05 v1(75.4,45.55) ; v1@75.25,45.55 ccw(c74.888,45.55) 75.144,45.806 ccw(c75.4,46.062) v1@75.4,45.7 ; v1@75.5,37.35 cw(c75.5,36.988) 75.756,37.244 cw(c76.012,37.5) v1@75.65,37.5 ; v1(75.5,37.5) C191.2@76,37 ; v2(76.35,71) 76.4,71 v2@76.381,70.981
  Bottom Layer w0.3: C212.2@56,46 56.975,45.025 58.975,45.025 C210.2@59,45 ; v1(58.5,40.4) 59.4,40.4 v1(59.5,40.5) ; v1(62.5,37.5) 62.925,37.925 62.925,38.697 63.025,38.797 63.025,40.025 v1(63.5,40.5) v1(63.5,41.5) ; v1@65.5,37.65 66.025,38.175 66.025,40.1 66.5,40.575 v1(66.5,41.5) ; v1(71.5,47.5) 72.025,48.025 72.025,48.697 71.975,48.747 71.975,51.025 v1(71.5,51.5) ; v2(84.15,42.5) 85.8,44.15 96.7,44.15 99.075,46.525 102.175,46.525 103.6,45.1 113.4,45.1 v1(115.55,47.25)
+2,5VLMS-1: C65-1.1 C68-1.1 C70-1.1 L17-1.1 R99-1.2 R102-1.1 R103-1.1 R154-1.1 R157-1.2 R158-1.1 U30-1.2 | length 77.2
  Top Layer w0.15: v1@116.006,14.68 ccw(c115.751,14.934) 116.111,14.934 ; v1(116.112,14.574) R154-1.1@116.111,17.058 ; 116.111,14.937 ccw(c116.476,14.937) v1@116.218,14.68 ; R158-1.1@116.111,21.358 116.561,20.908 ; R158-1.1@116.128,21.341 cw(c115.445,20.658) v1@116.411,20.658 ; R158-1.1@116.384,21.085 cw(c115.958,20.658) v1(116.561,20.658) 116.561,20.908 ; v1@116.49,20.791 ccw(c116.428,20.908) 116.561,20.908 ; v1@116.632,20.791 cw(c116.694,20.908) 116.561,20.908
  Top Layer w0.2: C68-1.1@119.357,11.188 119.461,11.292 v1(119.461,12.208) R103-1.1@119.461,13.108 ; v1@119.373,12.12 cw(c119.159,11.906) 119.461,11.906 cw(c119.763,11.906) v1@119.549,12.12 ; v1@119.373,12.297 ccw(c119.159,12.51) 119.461,12.51 ccw(c119.763,12.51) v1@119.549,12.297 ; 132.03,16.884 cw(c131.3,16.154) v1@132.333,16.154 ; R157-1.2@132.261,17.908 131.981,17.629 131.981,16.933 132.458,16.457 ; v1@132.37,16.242 ccw(c132.156,16.456) 132.458,16.456 ; 132.372,16.543 cw(c131.983,16.154) v1@132.533,16.154 ; v1(132.458,16.154) 132.458,16.457 ; v1@132.546,16.242 cw(c132.76,16.456) 132.458,16.456
  Top Layer w0.3: C70-1.1@145.4,10.4 R99-1.2@146.308,10.4
  Top Layer w0.5: R99-1.2@146.584,10.366 v3(147.35,10.366) 148.705,10.366 U30-1.2@148.79,10.281 ; C65-1.1@149.2,14.6 149.9,13.9 150.35,13.9 cw(c150.35,13.332) v3@150.772,13.713 ; 150.314,13.9 cw(c150.314,13.248) v3@150.775,13.709 ; U30-1.2@155.09,10.281 155.952,10.281 v3(157.174,9.059) ; 156.552,9.681 cw(c155.929,9.059) v3@156.81,9.059
  Top Layer w1: U30-1.2@148.79,10.281 U30-1.2@155.09,10.281
  Mid-Layer 2 w0.5: v1(116.561,20.658) 116.172,20.269 116.172,12.83 117.471,11.53 119.461,11.53 ; v1(119.461,12.208) 119.461,11.53 ; v1(132.458,16.154) 132.458,15.494 133.606,14.346 133.606,11.53 ; v3@147.4,10.35 134.786,10.35 133.606,11.53 ; 119.461,11.53 133.606,11.53
  Bottom Layer w0.15: v1@116.455,20.552 cw(c116.199,20.296) 116.561,20.296 cw(c116.923,20.296) v1@116.667,20.552 ; v1@116.455,20.764 ccw(c116.199,21.02) 116.561,21.02 ccw(c116.923,21.02) v1@116.667,20.764 ; R102-1.1@116.561,19.658 v1(116.561,20.658) L17-1.1@116.561,22.408
  other v3: 152.795,6.633 156.91,6.633 155.047,6.676 150.846,6.72 156.91,9.059 156.953,11.398 150.846,13.78 153.055,13.823 155.09,13.823
+2,5VLMS-2: C65-2.1 C68-2.1 C70-2.1 L17-2.1 R99-2.2 R102-2.1 R103-2.1 R154-2.1 R157-2.2 R158-2.1 U30-2.2 | length 74.8
  Top Layer w0.15: v1@116.045,63.972 ccw(c115.79,64.226) 116.15,64.226 ; v1(116.151,63.865) R154-2.1@116.15,66.35 ; 116.15,64.229 ccw(c116.515,64.229) v1@116.257,63.972 ; R158-2.1@116.15,70.65 116.6,70.2 ; R158-2.1@116.167,70.633 cw(c115.484,69.95) v1@116.45,69.95 ; R158-2.1@116.423,70.377 cw(c115.996,69.95) v1(116.6,69.95) 116.6,70.2 ; v1@116.529,70.082 ccw(c116.467,70.2) 116.6,70.2 ; v1@116.671,70.082 cw(c116.733,70.2) 116.6,70.2
  Top Layer w0.2: C68-2.1@119.396,60.48 119.5,60.584 v1(119.5,61.5) R103-2.1@119.5,62.4 ; v1@119.412,61.412 cw(c119.198,61.198) 119.5,61.198 cw(c119.802,61.198) v1@119.588,61.412 ; v1@119.412,61.588 ccw(c119.198,61.802) 119.5,61.802 ccw(c119.802,61.802) v1@119.588,61.588 ; 132.069,66.176 cw(c131.339,65.446) v1@132.372,65.446 ; R157-2.2@132.3,67.2 132.02,66.92 132.02,66.225 132.497,65.749 v1(132.497,65.446) ; v1@132.408,65.534 ccw(c132.195,65.748) 132.497,65.748 ccw(c132.799,65.748) v1@132.585,65.534 ; 132.411,65.835 cw(c132.022,65.446) v1@132.572,65.446
  Top Layer w0.3: v3@142.8,60.1 cw(c142.8,59.617) 143.141,59.959 cw(c143.483,60.3) v3@143,60.3 ; v3(142.8,60.3) 143.189,59.911 146.3,59.911 R99-2.2@146.534,59.911
  Top Layer w0.5: R99-2.2@146.334,59.861 148.455,59.861 U30-2.2@148.54,59.776 ; C65-2.1@149.1,64.2 149.4,63.9 149.971,63.9 v3(150.596,63.275) ; U30-2.2@155.04,59.926 155.902,59.926 v3(157.124,58.704)
  Top Layer w1: U30-2.2@148.54,59.776 U30-2.2@154.84,59.776
  Mid-Layer 2 w0.5: v1(116.6,69.95) 116.211,69.561 116.211,62.121 117.51,60.822 119.5,60.822 ; v1(119.5,61.5) 119.5,60.822 ; v1(132.497,65.446) 132.497,64.785 133.645,63.638 133.645,60.822 ; v3@142.75,60.3 134.167,60.3 133.645,60.822 ; 119.5,60.822 133.645,60.822
  Mid-Layer 2 w0.7: v3@142.75,60.3 v3(142.8,60.3)
  Bottom Layer w0.15: v1@116.494,69.844 cw(c116.238,69.588) 116.6,69.588 cw(c116.962,69.588) v1@116.706,69.844 ; v1@116.494,70.056 ccw(c116.238,70.312) 116.6,70.312 ccw(c116.962,70.312) v1@116.706,70.056 ; R102-2.1@116.6,68.95 v1(116.6,69.95) L17-2.1@116.6,71.7
  other v3: 152.545,56.129 150.596,56.215 156.86,56.279 154.997,56.322 156.903,61.043 152.805,63.319 155.04,63.469
+2,5VRAM: C158.1 C164.1 C168.1 C215.2 C216.2 C217.2 C218.2 C219.2 C220.2 C221.2 C222.2 C223.2 C224.2 C225.2 C226.2 C227.2 L43.2 U11.4 U11.11 U11.15 U11.20 U11.27 U11.41 U11.54 U11.61 U11.65 U11.70 U11.76 U11.77 U11.91 U11.97 | length 50
  Top Layer w0.2: U11.41@56.825,10.625 v2(58.075,10.625) ; v2@57.969,10.519 ccw(c57.713,10.263) 57.713,10.625 ccw(c57.713,10.987) v2@57.969,10.731 ; v2@59.869,2.181 ccw(c59.613,2.437) 59.975,2.437 ccw(c60.337,2.437) v2@60.081,2.181 ; v2@59.869,17.431 ccw(c59.613,17.687) 59.975,17.687 ccw(c60.337,17.687) v2@60.081,17.431 ; v2(59.975,2.075) U11.54@59.975,3.325 ; v2(59.975,17.325) U11.27@59.975,18.575 ; v2@64.419,2.181 ccw(c64.163,2.437) 64.525,2.437 ccw(c64.887,2.437) v2@64.631,2.181 ; v2@64.419,17.431 ccw(c64.163,17.687) 64.525,17.687 ccw(c64.887,17.687) v2@64.631,17.431 ; v2(64.525,2.075) U11.61@64.525,3.325 ; v2(64.525,17.325) U11.20@64.525,18.575 ; v2@67.019,2.181 ccw(c66.763,2.437) 67.125,2.437 ccw(c67.487,2.437) v2@67.231,2.181 ; v2(67.125,2.075) U11.65@67.125,3.325 ; v2@67.669,17.431 ccw(c67.413,17.687) 67.775,17.687 ccw(c68.137,17.687) v2@67.881,17.431 ; v2(67.775,17.325) U11.15@67.775,18.575 ; v2@70.269,2.181 ccw(c70.013,2.437) 70.375,2.437 ccw(c70.737,2.437) v2@70.481,2.181 ; v2@70.269,17.431 ccw(c70.013,17.687) 70.375,17.687 ccw(c70.737,17.687) v2@70.481,17.431 ; v2(70.375,2.075) U11.70@70.375,3.325 ; v2(70.375,17.325) U11.11@70.375,18.575 ; U11.76@74.275,3.325 74.275,2.375 v2(74.6,2.05) 74.925,2.375 U11.77@74.925,3.325 ; v2@74.45,2.05 ccw(c74.088,2.05) 74.344,2.306 ccw(c74.6,2.562) 74.6,2.2 ccw(c74.6,2.562) 74.856,2.306 ccw(c75.112,2.05) v2@74.75,2.05 ; v2@74.819,17.431 ccw(c74.563,17.687) 74.925,17.687 ccw(c75.287,17.687) v2@75.031,17.431 ; v2(74.925,17.325) U11.4@74.925,18.575 ; v2(76.825,11.275) U11.91@78.075,11.275 ; v2(76.825,15.175) U11.97@78.075,15.175 ; v2@76.931,11.169 cw(c77.187,10.913) 77.187,11.275 cw(c77.187,11.637) v2@76.931,11.381 ; v2@76.931,15.069 cw(c77.187,14.813) 77.187,15.175 cw(c77.187,15.537) v2@76.931,15.281
  Top Layer w0.3: C168.1@48.1,4.55 48.2,4.45 v5@50.4,4.45 ; L43.2@50.5,5.5 50.4,5.4 v5@50.4,4.45 ; v5@52.423,3.423 ccw(c51.996,2.996) 51.996,3.6 ccw(c51.996,4.204) v5@52.423,3.777 ; v5(52.6,3.6) 51.5,3.6 C164.1@51.4,3.6 50.45,3.6 C158.1@50.4,3.55 v5@50.4,4.45
  Bottom Layer w0.2: C219.2@57.45,10.4 57.675,10.625 v2(58.075,10.625) ; v2@57.969,10.519 ccw(c57.713,10.263) 57.713,10.625 ccw(c57.713,10.987) v2@57.969,10.731 ; C218.2@59.8,2.7 59.975,2.525 v2(59.975,2.075) ; C220.2@59.8,17.95 59.975,17.775 v2(59.975,17.325) ; v2@59.869,2.181 ccw(c59.613,2.437) 59.975,2.437 ccw(c60.337,2.437) v2@60.081,2.181 ; v2@59.869,17.431 ccw(c59.613,17.687) 59.975,17.687 ccw(c60.337,17.687) v2@60.081,17.431 ; v2@64.419,2.181 ccw(c64.163,2.437) 64.525,2.437 ccw(c64.887,2.437) v2@64.631,2.181 ; v2@64.419,17.431 ccw(c64.163,17.687) 64.525,17.687 ccw(c64.887,17.687) v2@64.631,17.431 ; v2(64.525,2.075) 64.525,2.475 C216.2@64.75,2.7 ; v2(64.525,17.325) 64.525,17.775 C221.2@64.7,17.95 ; v2@67.019,2.181 ccw(c66.763,2.437) 67.125,2.437 ccw(c67.487,2.437) v2@67.231,2.181 ; v2(67.125,2.075) 67.125,2.625 C215.2@67.2,2.7 ; C222.2@67.55,17.95 67.775,17.725 v2(67.775,17.325) ; v2@67.669,17.431 ccw(c67.413,17.687) 67.775,17.687 ccw(c68.137,17.687) v2@67.881,17.431 ; C224.2@70.15,17.95 70.375,17.725 v2(70.375,17.325) ; C217.2@70.2,2.7 70.375,2.525 v2(70.375,2.075) ; v2@70.269,2.181 ccw(c70.013,2.437) 70.375,2.437 ccw(c70.737,2.437) v2@70.481,2.181 ; v2@70.269,17.431 ccw(c70.013,17.687) 70.375,17.687 ccw(c70.737,17.687) v2@70.481,17.431 ; v2@74.494,2.156 ccw(c74.238,2.412) 74.6,2.412 ccw(c74.962,2.412) v2@74.706,2.156 ; v2(74.6,2.05) C223.2@74.6,2.85 ; v2@74.819,17.431 ccw(c74.563,17.687) 74.925,17.687 ccw(c75.287,17.687) v2@75.031,17.431 ; v2(74.925,17.325) 74.925,17.775 C225.2@75.1,17.95 ; v2(76.825,11.275) 76.9,11.35 C227.2@77.55,11.35 ; v2(76.825,15.175) 77.375,15.175 C226.2@77.55,15 ; v2@76.931,11.169 cw(c77.368,10.732) C227.2@77.368,11.35 ; v2@76.931,15.069 cw(c77.187,14.813) 77.187,15.175 cw(c77.187,15.537) v2@76.931,15.281
  other v5: 50.4,4.4
+2,5VRF: C294.2 C295.2 L48.2 U20.8 U22.8 | length 8.7
  Top Layer w0.15: U22.8@119.651,49.556 118.556,49.556 118.2,49.2 C295.2@118.2,48.625 L48.2@118.2,47.35 118.2,44.9 118.619,44.481 U20.8@119.701,44.481
  Top Layer w0.2: C294.2@119.701,43.356 U20.8@119.701,44.481
+3,0VCC: C1.1 C2.1 C12.1 C13.1 C312.1 L2.2 R3.1 R8.2 U4.3 U26.1 U28.2 | length 80.9
  Top Layer w0.2: R8.2@96.45,100.1 97.2,100.1 97.5,100.4 U28.2@97.5,102.3 ; v2@131.494,96.544 cw(c131.22,96.27) 131.608,96.27 ; v2(131.6,96.65) v2@131.608,96.65 ; v2@131.6,96.8 ccw(c131.6,97.404) 132.027,96.977 ; U26.1@131.608,95.97 v2@131.608,96.65 ; 131.608,96.306 cw(c131.944,96.306) v2@131.706,96.544 ; C312.1@132.192,97.142 C312.1@132.19,97.14 ; C312.1@132.403,97.14 C312.1@132.19,97.14 ; v2(139.25,99.05) L2.2@140.1,99.05 ; v2@139.356,98.944 cw(c139.612,98.688) 139.612,99.05 cw(c139.612,99.412) v2@139.356,99.156 ; L2.2@140.05,99.1 L2.2@140.1,99.1 ; U4.3@156.55,103.28 156.58,103.25 C2.1@158.2,103.25 v1(158.2,103.95) ; v1@158.112,103.862 cw(c157.898,103.648) 158.2,103.648 cw(c158.502,103.648) v1@158.288,103.862 ; v2@131.608,96.65 131.7,96.65 C312.1@132.19,97.14
  Top Layer w0.3: U4.3@156.55,103.28 C2.1@158.2,103.28 ; C2.1@158.35,103.25 C1.1@159.15,103.25
  Top Layer w1: 97.4,106.1 97.4,102.4 U28.2@97.5,102.3
  Bottom Layer w0.3: v2(103.15,105.8) 103.15,102.8 109.25,96.7 131.4,96.7 131.6,96.5 v2(131.6,96.65) 133.95,99 139.2,99 v2(139.25,99.05) ; 131.238,96.7 cw(c131.238,96.288) v2@131.529,96.579 ; 138.888,99 ccw(c138.888,99.412) v2@139.179,99.121 ; v2@139.3,99.05 v2(139.25,99.05) ; v1(158.2,103.95) 144.15,103.95 v2(139.25,99.05)
+3,3V1: C136.1 C141.1 C147.1 C150.1 C279.1 L36.1 L40.1 R136.1 R173.1 R174.1 U35.2 U35.7 | length 79.4
  Top Layer w0.3: L36.1@57.25,84.25 57.25,83.65 L36.1@57.95,82.95 ; C136.1@58.35,81.6 58.45,81.5 R136.1@60.7,81.5 ; L40.1@70.75,68.5 70.55,68.7 C150.1@70.55,69.65 70.6,69.6 v2(71.3,69.6) C147.1@71.95,69.6 ; v2(90.25,70.8) 91.35,69.7 91.35,62.3 93.9,59.75 95.9,59.75 96.55,60.4 R174.1@96.55,61.1 R173.1@96.55,62.45 ; U35.2@96.535,70.191 96.535,66.9 ; R173.1@96.6,62.55 96.535,62.615 U35.7@96.535,64.603 96.535,66.9 ; C279.1@99.35,66.9 96.535,66.9
  Top Layer w0.5: C141.1@54.15,81.25 54.6,81.7 v2(56.2,81.7) v2(57.2,81.7) 57.8,81.7 57.95,81.85 L36.1@57.95,82.95
  Mid-Layer 2 w0.3: v2(71.3,69.6) 79,69.6 80.2,70.8 v2(90.25,70.8)
  Mid-Layer 2 w0.5: v2(56.2,81.7) v2(57.2,81.7) 59.2,81.7 v2(71.3,69.6)
+3,3VETH: C37.1 C38.1 C39.1 L5.1 R64.2 U10.4 | length 15
  Top Layer w0.15: U10.4@33.49,60.1 34.14,59.45 C37.1@35.4,59.45 35.4,60.6 R64.2@35.5,60.7
  Top Layer w0.3: R64.2@35.5,60.7 36.95,60.7 38.3,62.05 41.05,62.05 43.35,59.75 L5.1@43.35,59 43.45,59.1 C39.1@44.75,59.1
+3,3VFPGA: C25.1 C27.2 C42.1 C159.1 C161.1 C165.1 C174.2 C194.2 C196.2 C197.2 C198.2 C199.2 C200.2 C201.2 C202.2 C203.2 C246.1 C247.1 C248.1 C249.1 C250.1 C251.1 C252.1 C254.1 C255.1 C256.1 C257.1 C258.1 C259.1 J1.1 L5.2 L40.2 R18.1 R19.1 R21.1 R22.1 R26.1 R27.1 R28.1 R29.1 R30.1 R31.2 R33.1 R34.1 R35.1 R36.1 R37.1 R38.1 R94.1 R151.1 R152.1 U6.7 U6.8 U7.8 U8.AA3 U8.AA7 U8.AA11 U8.AA15 U8.AA19 U8.D16 U8.F11 U8.G12 U8.H9 U8.H15 U8.K15 U8.L8 U8.M15 U8.N8 U8.R6 U8.R10 U8.R12 U8.R17 U8.T9 U8.T13 U8.U11 U8.V6 U8.V8 U8.V12 U8.V16 U8.W5 X1.2 X2.2 | length 270.3
  Top Layer w0.2: U8.AA19@58,56 v1(58.5,55.5) ; v1@58.35,55.5 ccw(c57.988,55.5) 58.244,55.756 ccw(c58.5,56.012) v1@58.5,55.65 ; U8.R17@60,50 v1(60.5,49.5) ; v1@60.35,49.5 ccw(c59.988,49.5) 60.244,49.756 ccw(c60.5,50.012) v1@60.5,49.65 ; U8.D16@61,39 v1(61.5,39.5) ; U8.V16@61,53 v1(61.5,52.5) ; v1@61.35,39.5 cw(c60.988,39.5) 61.244,39.244 cw(c61.5,38.988) v1@61.5,39.35 ; v1@61.35,52.5 ccw(c60.988,52.5) 61.244,52.756 ccw(c61.5,53.012) v1@61.5,52.65 ; v1@61.5,43.35 cw(c61.5,42.988) 61.756,43.244 cw(c62.012,43.5) v1@61.65,43.5 ; v1(61.5,43.5) U8.H15@62,43 ; v1@61.5,45.35 cw(c61.5,44.988) 61.756,45.244 cw(c62.012,45.5) v1@61.65,45.5 ; v1(61.5,45.5) U8.K15@62,45 ; v1(61.5,46.5) U8.M15@62,47 ; v1@61.5,46.65 ccw(c61.5,47.012) 61.756,46.756 ccw(c62.012,46.5) v1@61.65,46.5 ; U8.AA15@62,56 v1(62.5,55.5) ; v1@62.35,55.5 ccw(c61.988,55.5) 62.244,55.756 ccw(c62.5,56.012) v1@62.5,55.65 ; U8.T13@64,51 v1(64.5,50.5) ; v1@64.35,50.5 ccw(c63.988,50.5) 64.244,50.756 ccw(c64.5,51.012) v1@64.5,50.65 ; v1@64.5,50.35 cw(c64.5,49.988) 64.756,50.244 cw(c65.012,50.5) v1@64.65,50.5 ; v1(64.5,50.5) U8.R12@65,50 ; U8.G12@65,42 v1(65.5,41.5) U8.F11@66,41 ; U8.V12@65,53 v1(65.5,52.5) U8.U11@66,52 ; v1@65.35,41.5 ccw(c64.988,41.5) 65.244,41.756 ccw(c65.5,42.012) v1@65.5,41.65 ; v1@65.35,52.5 ccw(c64.988,52.5) 65.244,52.756 ccw(c65.5,53.012) v1@65.5,52.65 ; v1@65.5,41.35 cw(c65.5,40.988) 65.756,41.244 cw(c66.012,41.5) v1@65.65,41.5 ; v1@65.5,52.35 cw(c65.5,51.988) 65.756,52.244 cw(c66.012,52.5) v1@65.65,52.5 ; U8.AA11@66,56 v1(66.5,55.5) ; v1@66.35,55.5 ccw(c65.988,55.5) 66.244,55.756 ccw(c66.5,56.012) v1@66.5,55.65 ; U8.R10@67,50 v1(67.5,50.5) U8.T9@68,51 ; v1@67.35,50.5 cw(c66.988,50.5) 67.244,50.244 cw(c67.5,49.988) v1@67.5,50.35 ; v1(67.5,42.5) U8.H9@68,43 ; v1@67.5,42.65 ccw(c67.5,43.012) 67.756,42.756 ccw(c68.012,42.5) v1@67.65,42.5 ; v1@67.5,50.65 ccw(c67.5,51.012) 67.756,50.756 ccw(c68.012,50.5) v1@67.65,50.5 ; v1(68.5,52.5) U8.V8@69,53 ; v1@68.5,52.65 ccw(c68.5,53.012) 68.756,52.756 ccw(c69.012,52.5) v1@68.65,52.5 ; U8.L8@69,46 v1(69.5,46.5) ; U8.N8@69,48 v1(69.5,47.5) ; v1@69.35,46.5 cw(c68.988,46.5) 69.244,46.244 cw(c69.5,45.988) v1@69.5,46.35 ; v1@69.35,47.5 ccw(c68.988,47.5) 69.244,47.756 ccw(c69.5,48.012) v1@69.5,47.65 ; v1(69.5,55.5) U8.AA7@70,56 ; v1@69.5,55.65 ccw(c69.5,56.012) 69.756,55.756 ccw(c70.012,55.5) v1@69.65,55.5 ; v1(70.5,49.5) U8.R6@71,50 ; v1@70.5,49.65 ccw(c70.5,50.012) 70.756,49.756 ccw(c71.012,49.5) v1@70.65,49.5 ; U8.V6@71,53 v1(71.5,53.5) U8.W5@72,54 ; v1@71.35,53.5 cw(c70.988,53.5) 71.244,53.244 cw(c71.5,52.988) v1@71.5,53.35 ; v1@71.5,53.65 ccw(c71.5,54.012) 71.756,53.756 ccw(c72.012,53.5) v1@71.65,53.5 ; v1(73.5,55.5) U8.AA3@74,56 ; v1@73.5,55.65 ccw(c73.5,56.012) 73.756,55.756 ccw(c74.012,55.5) v1@73.65,55.5
  Top Layer w0.3: U7.8@29.647,71.147 v2(31.365,71.147) v2@31.429,71.147 ; v2@31.295,71.218 ccw(c31.041,71.472) 31.4,71.472 ; R26.1@31.34,70.146 31.34,71.057 v2@31.429,71.147 ; 31.34,70.844 cw(c31.669,70.844) v2@31.436,71.076 ; v2@31.4,71.182 C27.2@31.4,71.9 ; R27.1@32.517,70.12 32.517,70.833 32.203,71.147 v2@31.429,71.147 ; U6.7@42.611,68.339 43.8,68.339 v2(44.355,68.893) 44.354,68.894 C25.1@44.354,69.648 44.314,69.609 U6.8@42.611,69.609 ; L5.2@43.35,57.5 43.4,57.45 v2(44.15,57.45) C42.1@44.85,57.45 ; L40.2@70.75,66.2 R29.1@72.55,66.2 74.05,66.2 R30.1@74.1,66.15 ; R94.1@80.1,57.75 v1(81.05,57.75) ; R22.1@80.15,56.2 v1(81,56.2) v1@81.15,56.2 ; v2(83.75,26.6) 83.75,14.35 95.7,2.4 161.1,2.4 ; R35.1@162.5,2.4 R35.1@162.55,2.45 ; R28.1@164.95,16.2 R37.1@164.95,17.6 ; R33.1@166.05,2.4 161.1,2.4 ; R36.1@167.45,17.55 167.3,17.7 R38.1@162.45,17.7 161.5,17.7 161.1,17.3 161.1,2.4
  Top Layer w0.5: C165.1@68.05,63.3 68.15,63.4 v5(69.9,63.4) ; v5@69.9,63.445 C159.1@70.85,63.45 ; v5@70.007,63.295 cw(c70.372,62.933) 70.37,63.447 ; L40.2@70.75,66.2 70.95,66 C161.1@70.95,64.85 ; C161.1@70.842,64.95 70.843,64.849 C159.1@70.85,63.45 ; C159.1@70.9,63.45 C159.1@70.85,63.45 ; C159.1@70.9,63.5 C159.1@70.85,63.45
  Mid-Layer 2 w0.3: v1(67.5,42.5) 69.05,40.95 69.757,40.95 69.807,41 72.243,41 72.293,40.95 72.707,40.95 72.757,41 73.707,41 74,40.707 74,40.2 74.3,39.9 74.3,36.4 83.75,26.95 v2(83.75,26.6) ; 83.332,27.368 cw(c82.564,26.6) v2@83.65,26.6 ; 83.844,26.856 cw(c83.588,26.6) v2@83.95,26.6
  MidLayer1 w0.15: 69.05,47.75 69.1,47.8 69.1,48.75 69.5,49.15 70.05,49.15
  MidLayer1 w0.2: 59.8,55.95 59.85,56 61.25,56 ; 59.9,55.05 59.95,55 61,55 ; 61.05,47.05 61.05,48.05 ; v1(61.5,39.5) 61.524,39.5 62.024,40 66.1,40 66.3,40.2 ; v1@61.5,39.65 ccw(c61.5,40.012) 61.756,39.756 ccw(c62.012,39.5) v1@61.65,39.5 ; v1(61.5,43.5) 62.05,44.05 ; v1@61.5,43.65 ccw(c61.5,44.012) 61.756,43.756 ccw(c62.012,43.5) v1@61.65,43.5 ; v1@61.5,45.35 cw(c61.5,44.988) 61.756,45.244 cw(c62.012,45.5) v1@61.65,45.5 ; v1(61.5,45.5) 62.05,44.95 62.05,44.05 ; 62.9,46.15 62.95,46.1 62.95,44 ; 62.9,48.15 62.95,48.1 62.95,46.95 ; 65.15,41.95 65.039,42.061 63.539,42.061 63.539,43 ; 65.2,43 63.539,43 ; 67.9,49.1 68.05,48.95 68.05,48.1 68.15,48 ; 62.05,44.05 62.1,44 62.95,44 ; 62.95,44 62.95,43.241 63.191,43 63.539,43
  Bottom Layer w0.2: R19.1@42.1,38.6 43.1,38.6 v1(43.15,38.65) ; 42.728,38.6 ccw(c42.728,39.072) v1@43.062,38.738 ; v2(52.5,57.6) 52.6,57.6 52.65,57.55 R31.2@53.5,57.55 ; v2@52.606,57.706 ccw(c52.983,58.083) 52.983,57.55 ; R152.1@54.15,68.4 R152.1@54.45,68.4 v2(55.1,68.4) ; R151.1@54.241,65.893 55.093,65.893 v2(55.1,65.9) ; R151.1@54.72,65.893 ccw(c54.72,66.28) v2@54.994,66.006 ; R151.1@54.756,65.893 cw(c54.756,65.556) v2@54.994,65.794 ; v2@54.994,68.294 ccw(c54.738,68.038) 54.738,68.4 ccw(c54.738,68.762) v2@54.994,68.506 ; v1@58.5,55.35 cw(c58.5,54.988) 58.756,55.244 cw(c59.012,55.5) v1@58.65,55.5 ; v1(58.5,55.5) C251.1@59,55 ; R21.1@60.15,52.25 60.75,52.25 C199.2@61,52 ; v1@60.5,49.35 cw(c60.5,48.988) 60.756,49.244 cw(c61.012,49.5) v1@60.65,49.5 ; v1(60.5,49.5) C174.2@61,49 ; C249.1@60.95,46.95 C249.1@61,47 v1(61.5,46.5) ; C194.2@61,40 v1(61.5,39.5) ; C250.1@61,44 v1(61.5,43.5) C248.1@62,43 ; v1@61.35,39.5 ccw(c60.988,39.5) 61.244,39.756 ccw(c61.5,40.012) v1@61.5,39.65 ; v1@61.35,43.5 ccw(c60.988,43.5) 61.244,43.756 ccw(c61.5,44.012) v1@61.5,43.65 ; v1@61.35,46.5 ccw(c60.988,46.5) 61.244,46.756 ccw(c61.5,47.012) v1@61.5,46.65 ; v1@61.35,52.5 cw(c60.988,52.5) 61.244,52.244 cw(c61.5,51.988) v1@61.5,52.35 ; v1@61.5,43.35 cw(c61.5,42.988) 61.756,43.244 cw(c62.012,43.5) v1@61.65,43.5 ; v1@61.5,45.35 cw(c61.5,44.988) 61.756,45.244 cw(c62.012,45.5) v1@61.65,45.5 ; v1(61.5,45.5) C197.2@62,45 ; v1(61.5,52.5) C199.2@61,52 ; v1@62.5,55.35 cw(c62.5,54.988) 62.756,55.244 cw(c63.012,55.5) v1@62.65,55.5 ; v1(62.5,55.5) C201.2@63,55 ; C257.1@64,50 v1(64.5,50.5) ; v1@64.35,50.5 cw(c63.988,50.5) 64.244,50.244 cw(c64.5,49.988) v1@64.5,50.35 ; C246.1@65,42 v1(65.5,41.5) ; v1@65.35,41.5 ccw(c64.988,41.5) 65.244,41.756 ccw(c65.5,42.012) v1@65.5,41.65 ; v1@65.5,52.35 cw(c65.5,51.988) 65.756,52.244 cw(c66.012,52.5) 65.65,52.5 cw(c66.012,52.5) 65.756,52.756 cw(c65.5,53.012) v1@65.5,52.65 ; C203.2@66,52 v1(65.5,52.5) C247.1@66,53 ; v1@66.5,55.35 cw(c66.5,54.988) 66.756,55.244 cw(c67.012,55.5) v1@66.65,55.5 ; v1(66.5,55.5) C252.1@67,55 ; C196.2@67,43 v1(67.5,42.5) ; C258.1@67,50 v1(67.5,50.5) ; v1@67.35,42.5 ccw(c66.988,42.5) 67.244,42.756 ccw(c67.5,43.012) v1@67.5,42.65 ; v1@67.35,50.5 cw(c66.988,50.5) 67.244,50.244 cw(c67.5,49.988) v1@67.5,50.35 ; C256.1@68,53 v1(68.5,52.5) ; v1@68.35,52.5 ccw(c67.988,52.5) 68.244,52.756 ccw(c68.5,53.012) v1@68.5,52.65 ; C200.2@69,46 v1(69.5,46.5) ; C255.1@69,48 v1(69.5,47.5) ; v1@69.35,46.5 cw(c68.988,46.5) 69.244,46.244 cw(c69.5,45.988) v1@69.5,46.35 ; v1@69.35,47.5 ccw(c68.988,47.5) 69.244,47.756 ccw(c69.5,48.012) v1@69.5,47.65 ; v1@69.5,55.35 cw(c69.5,54.988) 69.756,55.244 cw(c70.012,55.5) v1@69.65,55.5 ; v1(69.5,55.5) C202.2@70,55 ; C259.1@70,50 v1(70.5,49.5) ; v1@70.35,49.5 ccw(c69.988,49.5) 70.244,49.756 ccw(c70.5,50.012) v1@70.5,49.65 ; C198.2@71,53 v1(71.5,53.5) ; v1@71.35,53.5 cw(c70.988,53.5) 71.244,53.244 cw(c71.5,52.988) v1@71.5,53.35 ; C254.1@73,55 v1(73.5,55.5) ; v1@73.35,55.5 cw(c72.988,55.5) 73.244,55.244 cw(c73.5,54.988) v1@73.5,55.35 ; C199.2@61,52 61.05,52 C199.2@61,52
  Bottom Layer w0.3: X1.2@32.45,37.1 33.388,38.038 R18.1@33.388,38.671
+3,3VLMS-1: C64-1.1 C69-1.1 L12-1.1 L13-1.1 L21-1.2 L22-1.1 L23-1.2 L24-1.1 L25-1.2 L26-1.1 L27-1.2 L28-1.1 L29-1.2 R95-1.2 U29-1.2 | length 45.9
  Top Layer w0.15: L26-1.1@131.907,21.588 131.937,21.558 132.461,21.558 132.661,21.758 ; v1@132.571,21.938 cw(c132.436,21.758) 132.661,21.758 ; v1@132.751,21.938 ccw(c132.886,21.758) 132.661,21.758 ; v1@132.761,22.058 132.661,21.958 132.661,21.758
  Top Layer w0.2: L21-1.2@120.161,27.808 120.811,28.458 ; L21-1.2@120.386,28.033 cw(c121.111,27.307) v1@121.111,28.333 ; 120.727,28.374 cw(c121.111,27.99) v1@121.111,28.533 ; v1@121.022,28.37 ccw(c120.811,28.161) 120.811,28.458 ; v1@121.022,28.546 cw(c120.811,28.756) 120.811,28.458 ; v1(121.111,28.458) 120.811,28.458 ; L29-1.2@127.607,10.538 128.241,10.538 128.607,10.904 v1@128.607,12.412 ; v1@127.823,28.27 cw(c127.619,28.066) 127.907,28.066 ; L25-1.2@127.907,27.488 127.907,28.354 v1(127.911,28.358) ; 127.907,28.047 cw(c128.223,28.047) v1@127.999,28.27 ; v1@128.523,12.32 cw(c128.319,12.116) 128.607,12.116 ; v1@128.523,12.497 ccw(c128.319,12.7) 128.607,12.7 ; 128.607,12.097 cw(c128.923,12.097) v1@128.699,12.32 ; 128.607,12.72 ccw(c128.923,12.72) v1@128.699,12.497 ; L22-1.1@128.607,13.238 v1@128.607,12.412 ; v1(128.611,12.408) v1@128.607,12.412 ; L28-1.1@131.907,27.238 132.841,27.238 v1(132.861,27.258) ; 132.511,27.238 ccw(c132.511,27.609) v1@132.773,27.347 ; 132.608,27.238 cw(c132.608,27.005) v1@132.773,27.17
  Top Layer w0.3: C64-1.1@143.25,29.65 143.25,28.8 143.6,28.45 C69-1.1@144.85,28.45 152.7,28.45 U29-1.2@153.75,27.4
  Top Layer w1: v3@156.762,27.413 v3(156.951,27.225)
  Mid-Layer 2 w0.5: v2(132.566,16.988) 131.85,17.704 131.85,21.247 v1(132.661,22.058) 132.636,22.083 132.373,22.083 131.8,22.656 131.8,25 132.861,26.061 v1(132.861,27.258)
  Bottom Layer w0.15: L13-1.1@131.907,20.988 R95-1.2@131.907,22.088 132.731,22.088 v1@132.761,22.058 ; R95-1.2@132.227,22.088 cw(c132.227,21.624) v1@132.555,21.952 ; 132.371,22.088 ccw(c132.371,22.348) v1@132.555,22.164
  Bottom Layer w0.2: v1(121.111,28.458) 121.587,28.458 L23-1.2@122.207,27.838 ; v1@121.199,28.37 cw(c121.413,28.156) 121.413,28.458 cw(c121.413,28.76) v1@121.199,28.547 ; L12-1.1@123.811,13.158 L27-1.2@124.911,13.158 L27-1.2@124.802,13.049 ; L27-1.2@124.711,12.958 L27-1.2@124.802,13.049 ; v1@124.714,10.633 ccw(c124.501,10.847) 124.802,10.847 ccw(c125.104,10.847) v1@124.891,10.633 ; v1(124.802,10.545) L27-1.2@124.802,13.049 ; L24-1.1@131.857,16.888 131.978,17.01 132.545,17.01 v2(132.566,16.988) ; L24-1.1@132.152,17.01 cw(c132.152,16.574) v2@132.46,16.882 ; L24-1.1@132.256,17.01 ccw(c132.256,17.298) v2@132.46,17.094
  other v3: 156.98,23.89 150.921,23.914 152.848,23.911 155.117,23.911 156.985,26.253 157.028,28.592 150.943,30.854 155.169,30.874 153.067,30.895
+3,3VLMS-2: C64-2.1 C69-2.1 L12-2.1 L13-2.1 L21-2.2 L22-2.1 L23-2.2 L24-2.1 L25-2.2 L26-2.1 L27-2.2 L28-2.1 L29-2.2 R95-2.2 U29-2.2 | length 39.4
  Top Layer w0.15: L26-2.1@131.946,70.88 131.976,70.85 132.5,70.85 132.7,71.05 ; v1@132.61,71.23 cw(c132.475,71.05) 132.7,71.05 ; v1@132.79,71.23 ccw(c132.925,71.05) 132.7,71.05 ; v1@132.8,71.35 132.7,71.25 132.7,71.05
  Top Layer w0.2: L21-2.2@120.2,77.1 120.85,77.75 ; L21-2.2@120.424,77.324 cw(c121.15,76.599) v1@121.15,77.625 ; 120.766,77.666 cw(c121.15,77.282) v1@121.15,77.825 ; v1@121.061,77.662 ccw(c120.85,77.453) 120.85,77.75 ; v1@121.061,77.838 cw(c120.85,78.047) 120.85,77.75 ; v1(121.15,77.75) 120.85,77.75 ; L29-2.2@127.646,59.83 128.28,59.83 128.646,60.196 v1@128.646,61.704 ; v1@127.862,77.562 cw(c127.658,77.358) 127.946,77.358 ; L25-2.2@127.946,76.78 127.946,77.646 v1(127.95,77.65) ; 127.946,77.338 cw(c128.262,77.338) v1@128.038,77.562 ; v1@128.562,61.612 cw(c128.358,61.408) 128.646,61.408 ; v1@128.562,61.788 ccw(c128.358,61.992) 128.646,61.992 ; 128.646,61.388 cw(c128.962,61.388) v1@128.738,61.612 ; 128.646,62.012 ccw(c128.962,62.012) v1@128.738,61.788 ; L22-2.1@128.646,62.53 v1@128.646,61.704 ; v1(128.65,61.7) v1@128.646,61.704 ; L28-2.1@131.946,76.53 132.88,76.53 v1(132.9,76.55) ; 132.55,76.53 ccw(c132.55,76.9) v1@132.812,76.638 ; 132.647,76.53 cw(c132.647,76.297) v1@132.812,76.462 ; v2@142.994,78.006 ccw(c142.738,78.262) 143.1,78.262 ccw(c143.462,78.262) v2@143.206,78.006 ; v2(143.1,77.9) C64-2.1@143.1,79.1 ; C69-2.1@146,77.7 152.735,77.7 U29-2.2@153.7,76.735
  Top Layer w1: U29-2.2@155.04,76.776 156.712,76.776 v3(156.901,76.588)
  Mid-Layer 2 w0.5: v2(132.605,66.28) 131.85,67.035 131.85,70.5 v1(132.7,71.35)
  Bottom Layer w0.15: L13-2.1@131.946,70.28 R95-2.2@131.946,71.38 132.77,71.38 v1@132.8,71.35 ; R95-2.2@132.266,71.38 cw(c132.266,70.916) v1@132.594,71.244 ; 132.41,71.38 ccw(c132.41,71.64) v1@132.594,71.456
  Bottom Layer w0.2: v1(121.15,77.75) 121.626,77.75 L23-2.2@122.246,77.13 ; v1@121.238,77.662 cw(c121.452,77.448) 121.452,77.75 cw(c121.452,78.052) v1@121.238,77.838 ; L12-2.1@123.85,62.45 L27-2.2@124.95,62.45 L27-2.2@124.841,62.341 ; L27-2.2@124.75,62.25 L27-2.2@124.841,62.341 ; v1@124.753,59.925 ccw(c124.539,60.139) 124.841,60.139 ccw(c125.143,60.139) v1@124.93,59.925 ; v1(124.841,59.837) L27-2.2@124.841,62.341 ; L24-2.1@131.896,66.18 132.017,66.301 132.584,66.301 v2(132.605,66.28) ; L24-2.1@132.191,66.301 cw(c132.191,65.865) v2@132.499,66.174 ; L24-2.1@132.295,66.301 ccw(c132.295,66.59) v2@132.499,66.386
  other v3: 150.671,73.127 152.598,73.124 156.93,73.253 155.067,73.274 156.935,75.616 156.978,77.955 150.693,80.067 152.817,80.108 155.119,80.237
+5V: C4.1 C139.1 C146.1 C288.1 L1.1 L39.1 L47.1 R126-1.2 R126-2.2 R134.1 U18.2 | length 108.5
  Top Layer w0.3: R134.1@101.15,82.9 U18.2@102.817,82.9 ; L1.1@102.6,100.2 102.65,100.25 C4.1@102.65,101.55 ; L39.1@110.55,44.332 111.782,43.1 v3(112.8,43.1) ; v1(115.111,39.933) 115.812,39.933 R126-1.2@115.912,40.033 ; v1(115.15,89.225) 115.851,89.225 R126-2.2@115.951,89.325 ; v1(120.85,47.15) C288.1@120.85,47.8 ; C288.1@120.9,47.8 L47.1@121.75,47.8 L47.1@121.8,47.8
  Top Layer w0.5: v3(102.6,99.1) L1.1@102.6,100.2 ; U18.2@102.79,82.927 102.817,82.9 U18.2@102.84,82.877
  Top Layer w1: U18.2@102.817,82.9 U18.2@109.298,82.9 ; C146.1@105.2,75.25 105.2,78.3 ; v3@105.202,79.286 cw(c104.706,78.794) 105.2,78.3 ; 105.3,78.4 105.2,78.3 ; v3@110.988,82.877 v3@111.022,82.843
  Mid-Layer 2 w0.3: v1(115.111,39.933) 113.567,39.933 112.75,40.75 112.75,44.3 113.5,45.05 113.5,86.05 113.35,86.2 113.35,87.425 v1(115.15,89.225)
  Mid-Layer 2 w1: v3(102.6,99.1) 102.6,88.736 v3(105.096,86.24) v3@109.297,86.24 ; v3(109.34,86.284) v3@109.297,86.24 ; 113.35,86.2 113.31,86.24 v3@109.297,86.24
  Bottom Layer w0.3: v3(112.8,43.1) 120.15,43.1 122.05,45 122.05,46.4 121.3,47.15 v1(120.85,47.15)
  other v3: 107.045,79.094 111.159,79.094 109.297,79.137 105.096,79.18 111.159,81.519 111.109,83.103 111.166,84.767 107.305,86.284
+5V2: C6.1 C7.1 C315.2 L1.2 R2.1 U27.8 U28.3 | length 53.3
  Top Layer w0.15: C315.2@142,97.25 v2(142.621,96.629) U27.8@142.621,95.986 ; v2@142.446,96.629 ccw(c142.023,96.629) 142.322,96.928 ccw(c142.621,97.227) v2@142.621,96.804 ; v2@142.497,96.506 cw(c142.198,96.207) 142.621,96.207 cw(c143.043,96.207) v2@142.744,96.506
  Top Layer w0.3: C7.1@99.35,100.2 100.15,100.2
  Top Layer w0.5: U28.3@99.8,102.3 100.1,102 100.1,100.25 100.15,100.2 L1.2@101.1,100.2 101.1,97.7 C6.1@101.8,97 102.8,96 v3(126.3,96) ; U28.3@100,103.05 100.05,103 R2.1@101.5,103
  Mid-Layer 2 w0.5: v3(126.3,96) 141.991,96 v2(142.621,96.629)
+5VRF: C292.1 C293.1 C296.1 C297.1 L47.2 L49.1 L50.1 U20.1 U22.1 | length 47.4
  Top Layer w0.2: C292.1@124.101,43.306 U20.1@124.101,44.481
  Top Layer w0.3: L47.2@123.25,47.8 123.05,47.6 123.05,44.7 123.269,44.481 U20.1@124.101,44.481 ; U22.1@124.051,49.556 123.206,49.556 123.05,49.4 v2(123.05,48.8) 123.05,48.05 123.3,47.8 123.35,47.85 C293.1@124.35,47.85 ; L50.1@149.65,51.7 v2(151.65,51.7) ; L49.1@149.751,46.256 C296.1@150.901,46.256 150.901,45.651 v2(150.9,45.65)
  Mid-Layer 2 w0.3: v2(123.05,48.8) 141,48.8 141.5,48.3 150.25,48.3 ; v2(150.9,45.65) 150.25,46.3 150.25,48.3 ; v2(151.65,51.7) 150.25,50.3 150.25,48.3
